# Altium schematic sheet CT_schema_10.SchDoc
size 274 x 160 mm
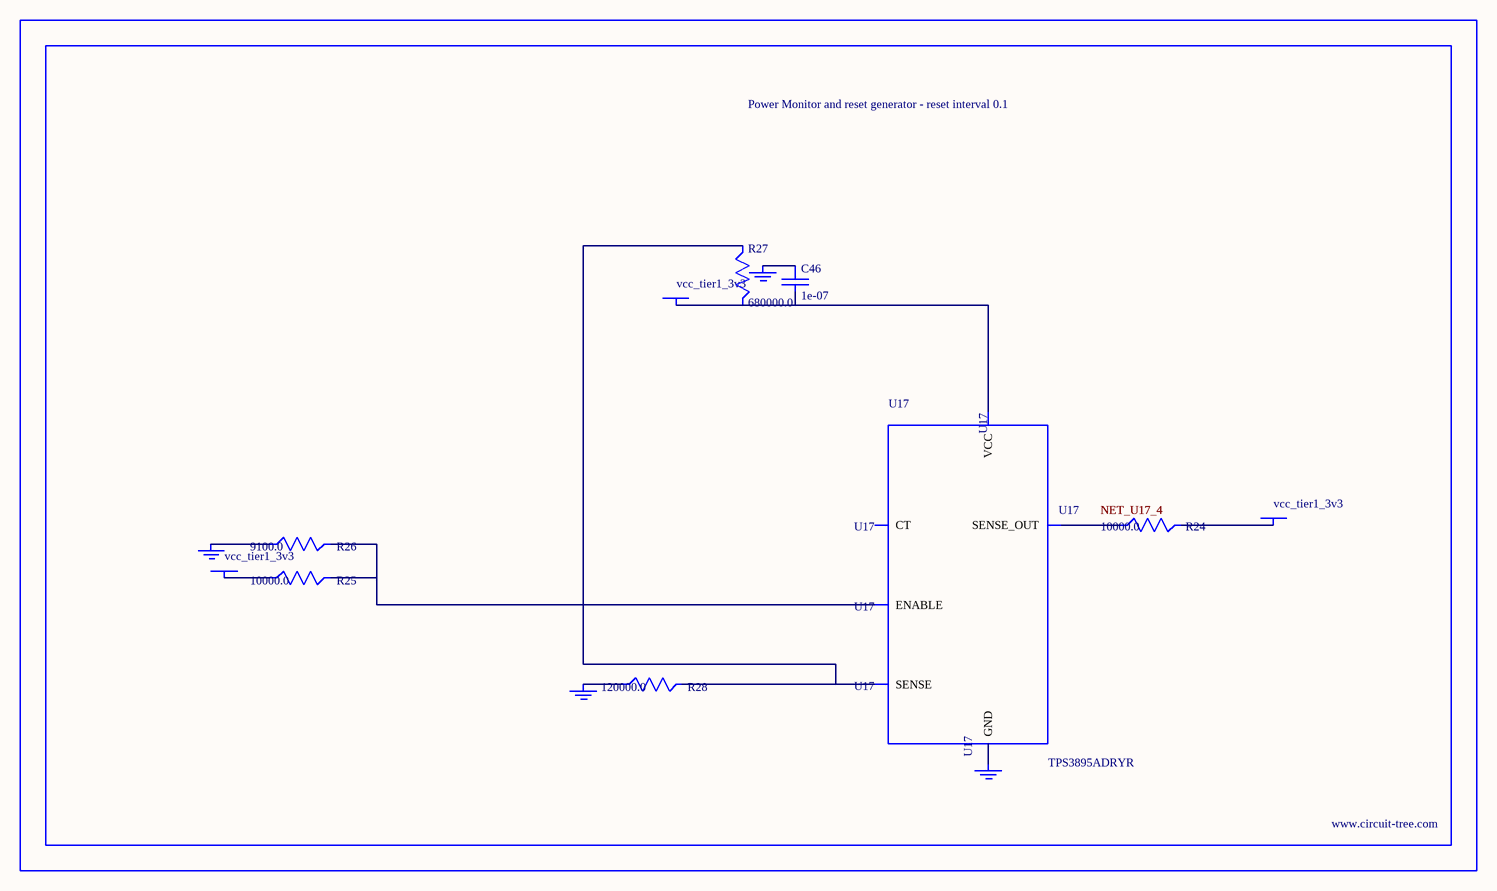
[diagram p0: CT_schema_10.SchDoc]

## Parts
BORDER9  (no value)
C46  1e-07  [C0402]
GND_INSTANCE_9_0  (no value)
GND_INSTANCE_9_1  (no value)
GND_INSTANCE_9_2  (no value)
GND_INSTANCE_9_3  (no value)
POWER_INSTANCE_9_0  vcc_tier1_3v3
POWER_INSTANCE_9_1  vcc_tier1_3v3
POWER_INSTANCE_9_2  vcc_tier1_3v3
R24  10000.0  [R0603]
R25  10000.0  [R0603]
R26  9100.0  [R0603]
R27  680000.0  [R0603]
R28  120000.0  [R0603]
U17  TPS3895ADRYR  [SON-6]

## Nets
NetC46_1: C46.1 GND_INSTANCE_9_2.0(GND)
NetC46_2: C46.2 POWER_INSTANCE_9_2.0(PWR) R27.2 U17.6(VCC)
NetGND_INSTANCE_9_0_0: GND_INSTANCE_9_0.0(GND) R26.1
NetGND_INSTANCE_9_1_0: GND_INSTANCE_9_1.0(GND) R28.1
NetGND_INSTANCE_9_3_0: GND_INSTANCE_9_3.0(GND) U17.2(GND)
NetPOWER_INSTANCE_9_0_0: POWER_INSTANCE_9_0.0(PWR) R25.1
NetPOWER_INSTANCE_9_1_0: POWER_INSTANCE_9_1.0(PWR) R24.2
NetR24_1: R24.1 U17.4(SENSE_OUT)
NetR25_2: R25.2 R26.2 U17.1(ENABLE)
NetR27_1: R27.1 R28.2 U17.3(SENSE)

Not connected (* = marked no-connect by the designer): U17 5(CT)

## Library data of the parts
BORDER9 = BORDER_PAGE9
C46 = C0402C104K3RACTU
GND_INSTANCE_9_0-GND_INSTANCE_9_3 = GND
POWER_INSTANCE_9_0-POWER_INSTANCE_9_2 = PWR
R24 R25 = RC0603JR-0710KL
R26 = RC0603JR-079K1L
R27 = RC0603JR-07680KL
R28 = RC0603JR-07120KL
